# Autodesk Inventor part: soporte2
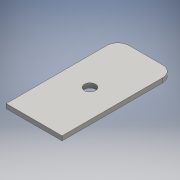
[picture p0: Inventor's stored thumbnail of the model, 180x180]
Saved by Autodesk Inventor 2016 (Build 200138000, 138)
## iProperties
Created: 2016-06
Part Number: soporte2
Material: Genérico
Document SubType Name: Modeling
Designer: adm
Density: 1 g/cm^3
Appearance: Valor por defecto
Author: adm
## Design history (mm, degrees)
sketch "Boceto1"
  geometry: L1 (-25, -50)-(25, -50); L2 (25, -50)-(25, 50); L3 (25, 50)-(-25, 50); L4 (-25, 50)-(-25, -50); L5 (-25, -50)-(25, 50); L6 (25, -50)-(-25, 50); C1 r 5 at (0, 0); 2 further points
  constraints: 12 end point, 2 midpoint, 2 parallel, 1 centre point, 1 coincident, 1 horizontal, 1 perpendicular
  dimensions: "d0" = 50 distance of L3.end L2.end; "d1" = 100 distance of L2.end L1.end; "d2" = 50 distance from line of point (0, 0) L3; "d3" = 10 diameter of C1
extrude "Extrusión1" new body sketch "Boceto1" distance "d4" = 4; taper "d5" = 0 deg
fillet "Empalme1" dims "d6" = 10
node "Sólido1"
